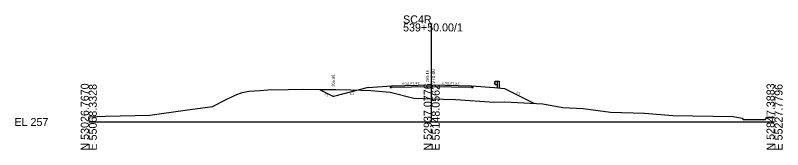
# Model space of a CAD drawing. Extents: x 9740 to 17409, y 8856 to 28416.
# Drawn here: x 11740.2 to 12008.7, y 20361.7 to 20408.7 of the extents above; entities that cross this region are included whole.
import ezdxf

# ---------------------------------------------------------------- set-up
doc = ezdxf.new("R2010")
doc.units = 0
for name, color, linetype in [('Level 10', 7, 'Continuous'), ('Level 11', 7, 'Continuous'), ('Level 12', 7, 'Continuous'), ('Level 24', 7, 'Continuous'), ('Level 32', 7, 'Continuous'), ('Level 33', 7, 'Continuous'), ('Level 59', 7, 'Continuous'), ('Level 6', 7, 'Continuous'), ('Level 60', 7, 'Continuous'), ('Level 63', 7, 'Continuous'), ('Level 7', 7, 'Continuous')]:
    doc.layers.add(name, color=color, linetype=linetype)

msp = doc.modelspace()

# ---------------------------------------------------------------- linework, layer by layer
at = {"layer": 'Level 11'}
for p, q in [((11871.85, 20383.79), (11871.35, 20383.78)), ((11871.35, 20383.78), (11871.35, 20383.44)), ((11871.35, 20383.44), (11871.85, 20383.45)), ((11871.85, 20384.09), (11871.85, 20383.79)), ((11899.85, 20383.79), (11899.85, 20384.09)), ((11900.35, 20383.78), (11899.85, 20383.79)), ((11899.85, 20383.45), (11900.35, 20383.44)), ((11900.35, 20383.44), (11900.35, 20383.78))]:
    msp.add_line(p, q, dxfattribs=at)
at = {"layer": 'Level 12'}
for p, q in [((11885.85, 20383.74), (11871.85, 20383.45)), ((11899.85, 20383.45), (11885.85, 20383.74))]:
    msp.add_line(p, q, dxfattribs=at)
at = {"layer": 'Level 24'}
for p, q in [((11908.12, 20385.6), (11907.85, 20385.4)), ((11907.85, 20385.4), (11907.85, 20385.35)), ((11907.85, 20385.35), (11908.12, 20385.15)), ((11907.85, 20384.83), (11908.12, 20385.03)), ((11907.85, 20384.78), (11907.85, 20384.83)), ((11908.12, 20384.58), (11907.85, 20384.78)), ((11908.12, 20384.51), (11908.12, 20385.67)), ((11908.12, 20385.67), (11908.79, 20385.67)), ((11908.12, 20384.51), (11908.79, 20384.51)), ((11908.79, 20385.67), (11908.79, 20383.34)), ((11908.79, 20385.67), (11909.46, 20385.67)), ((11909.46, 20385.67), (11909.46, 20383.29))]:
    msp.add_line(p, q, dxfattribs=at)
at = {"layer": 'Level 59'}
for p, q in [((11871.85, 20384.09), (11885.85, 20384.38)), ((11885.85, 20384.38), (11899.85, 20384.09))]:
    msp.add_line(p, q, dxfattribs=at)
at = {"layer": 'Level 6'}
for p, q in [((11863.69, 20383.41), (11871.85, 20384.09)), ((11899.85, 20384.09), (11907.85, 20383.42)), ((11907.85, 20383.42), (11911.35, 20383.13))]:
    msp.add_line(p, q, dxfattribs=at)
at = {"layer": 'Level 60'}
for p, q in [((11819.5, 20381.73), (11821.92, 20382.18)), ((11821.92, 20382.18), (11825.82, 20382.42)), ((11825.82, 20382.42), (11828.49, 20382.6)), ((11828.49, 20382.6), (11835.64, 20382.78)), ((11835.64, 20382.78), (11840.86, 20382.89)), ((11840.86, 20382.89), (11847.37, 20382.8)), ((11847.37, 20382.8), (11852.31, 20382.77)), ((11852.31, 20382.77), (11857.6, 20382.61)), ((11857.6, 20382.61), (11864.61, 20382.47)), ((11864.61, 20382.47), (11871.36, 20381.87)), ((11871.36, 20381.87), (11879.67, 20379.75)), ((11809.15, 20376.82), (11813.65, 20379.09)), ((11813.65, 20379.09), (11817.1, 20380.82)), ((11817.1, 20380.82), (11819.5, 20381.73)), ((11879.67, 20379.75), (11885.85, 20379.54)), ((11885.85, 20379.54), (11894.15, 20379.25)), ((11894.15, 20379.25), (11907.9, 20378.34)), ((11799.6, 20375.52), (11809.15, 20376.82)), ((11907.9, 20378.34), (11911.42, 20378.44)), ((11911.42, 20378.44), (11924.82, 20377.74)), ((11924.82, 20377.74), (11931.81, 20376.43)), ((11931.81, 20376.43), (11938.89, 20376.12)), ((11771.68, 20373.38), (11787.27, 20373.83)), ((11787.27, 20373.83), (11799.6, 20375.52)), ((11938.89, 20376.12), (11948.43, 20374.86)), ((11948.43, 20374.86), (11960.29, 20374.42)), ((11960.29, 20374.42), (11970.3, 20373.62)), ((11765.85, 20373.22), (11771.68, 20373.38)), ((11970.3, 20373.62), (11991.41, 20373.3)), ((11991.41, 20373.3), (11994.51, 20372.72)), ((11994.51, 20372.72), (11994.9, 20372.25)), ((11994.9, 20372.25), (12002.66, 20372.25)), ((12002.66, 20372.25), (12003.05, 20373.03)), ((12003.05, 20373.03), (12005.85, 20373.02))]:
    msp.add_line(p, q, dxfattribs=at)
at = {"layer": 'Level 63'}
for p, q in [((11885.85, 20371.38), (11885.85, 20405.91)), ((11765.85, 20371.38), (11885.85, 20371.38)), ((11885.85, 20371.38), (12005.85, 20371.38))]:
    msp.add_line(p, q, dxfattribs=at)
at = {"layer": 'Level 7'}
for p, q in [((11846.63, 20382.81), (11851.52, 20380.37)), ((11863.69, 20383.41), (11851.52, 20380.37)), ((11911.35, 20383.13), (11921.81, 20377.9))]:
    msp.add_line(p, q, dxfattribs=at)

# ---------------------------------------------------------------- texts
at = {"layer": 'Level 10'}
msp.add_text('265.16', height=1, rotation=90, dxfattribs=at).set_placement((11884.85, 20385.33))
at = {"layer": 'Level 32'}
for s, rotation, p in [('0.021 FT./FT.', 1.1916, (11875.56, 20384.42)), ('0.021 FT./FT.', 358.8084, (11889.57, 20384.55)), ('4:1', 14.0362, (11857.35, 20380.75)), ('2:1', 333.435, (11915.42, 20381.47)), ('2:1', 333.435, (11848.21, 20380.87))]:
    msp.add_text(s, height=0.75, rotation=rotation, dxfattribs=at).set_placement(p)
at = {"layer": 'Level 33'}
msp.add_text('265.98', height=1, rotation=90, dxfattribs=at).set_placement((11851.92, 20383.76))
at = {"layer": 'Level 59'}
msp.add_text(' 270.00', height=1.2, rotation=90, dxfattribs=at).set_placement((11887.05, 20384.38))
at = {"layer": 'Level 63'}
for s, p in [('SC4R', (11875.85, 20405.91)), ('539+50.00/1', (11875.85, 20403.11)), ('EL 257', (11739.85, 20369.98))]:
    msp.add_text(s, height=2.8, dxfattribs=at).set_placement(p)
for s, p in [('N 53026.7670', (11765.85, 20361.38)), ('E 55068.3328', (11768.65, 20361.38)), ('N 52937.0776', (11885.85, 20361.38)), ('E 55148.0562', (11888.65, 20361.38)), ('N 52847.3883', (12005.85, 20361.38)), ('E 55227.7796', (12008.65, 20361.38))]:
    msp.add_text(s, height=2.8, rotation=90, dxfattribs=at).set_placement(p)

doc.saveas('drawing.dxf')
